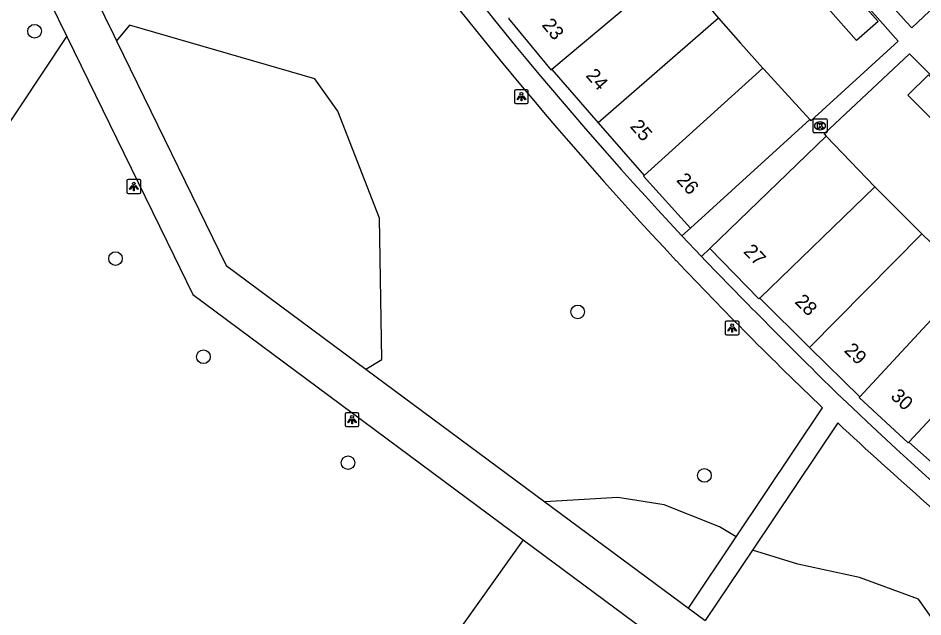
# Model space of a CAD drawing. Extents: x 160026 to 161302, y 384757 to 385701.
# Drawn here: x 160276.8 to 160341.6, y 385373.5 to 385416.5 of the extents above; entities that cross this region are included whole.
import ezdxf

# ---------------------------------------------------------------- set-up
doc = ezdxf.new("R2010")
doc.units = 0
for name, color, linetype in [('IMGEO_Boom', 7, 'Continuous'), ('IMGEO_Groenvoorziening', 7, 'Continuous'), ('IMGEO_Kolk', 7, 'Continuous'), ('IMGEO_Lichtpunt', 7, 'Continuous'), ('IMGEO_Pand', 7, 'Continuous'), ('IMGEO_Pand_nummerreeks', 7, 'Continuous'), ('IMGEO_Rijbaan_lokaal_open', 7, 'Continuous'), ('IMGEO_Voetpad_open', 7, 'Continuous')]:
    doc.layers.add(name, color=color, linetype=linetype)

msp = doc.modelspace()

# ---------------------------------------------------------------- linework, layer by layer
at = {"layer": 'IMGEO_Boom'}
for centre in [(160278.004, 385415.507), (160283.801, 385399.224), (160316.903, 385395.403), (160290.103, 385392.185), (160300.453, 385384.598), (160325.981, 385383.684)]:
    msp.add_circle(centre, 0.489, dxfattribs=at)
at = {"layer": 'IMGEO_Groenvoorziening'}
for points in [[(160301.742, 385391.306), (160302.881, 385391.991), (160302.706, 385402.128), (160299.735, 385409.79), (160298.089, 385412.09), (160284.8, 385415.949), (160283.874, 385414.83)], [(160263.246, 385389.432), (160280.314, 385415.136)], [(160328.251, 385379.283), (160327.068, 385380.008), (160323.107, 385381.576), (160319.769, 385382.102), (160314.554, 385381.8)], [(160313.003, 385379.066), (160306.615, 385370.103), (160315.68, 385363.866)], [(160348.057, 385365.324), (160341.324, 385374.825), (160337.094, 385376.363), (160332.682, 385377.332), (160329.427, 385378.337)]]:
    msp.add_lwpolyline(points, dxfattribs=at)
at = {"layer": 'IMGEO_Kolk'}
for p, q in [((160333.76, 385408.306), (160333.76, 385409.158)), ((160333.835, 385409.232), (160334.687, 385409.232)), ((160334.248, 385409.012), (160334.273, 385409.012)), ((160334.761, 385409.158), (160334.761, 385408.306)), ((160334.687, 385408.232), (160333.835, 385408.232)), ((160334.271, 385408.452), (160334.246, 385408.452))]:
    msp.add_line(p, q, dxfattribs=at)
for points in [[(160333.76, 385408.306), (160333.76, 385409.158)], [(160333.835, 385409.232), (160334.687, 385409.232)], [(160334.081, 385408.932), (160334.204, 385408.932), (160334.204, 385408.781), (160334.334, 385408.932), (160334.498, 385408.932), (160334.352, 385408.781), (160334.505, 385408.532), (160334.353, 385408.532), (160334.268, 385408.696), (160334.204, 385408.629), (160334.204, 385408.532), (160334.081, 385408.532), (160334.081, 385408.932)], [(160334.761, 385409.158), (160334.761, 385408.306)], [(160334.687, 385408.232), (160333.835, 385408.232)]]:
    msp.add_lwpolyline(points, dxfattribs=at)
for centre, start, end in [((160333.837, 385409.156), 91.55205, 178.44795), ((160333.837, 385409.156), 91.55205, 178.44795), ((160334.685, 385409.156), 1.55205, 88.44795), ((160334.685, 385409.156), 1.55205, 88.44795), ((160333.837, 385408.308), 181.55205, 268.44795), ((160333.837, 385408.308), 181.55205, 268.44795), ((160334.685, 385408.308), 271.55205, 358.44795), ((160334.685, 385408.308), 271.55205, 358.44795)]:
    msp.add_arc(centre, 0.0765, start, end, dxfattribs=at)
for centre, major_axis, ratio, start_param, end_param in [((160334.247, 385408.732), (-0.387, 0.002), 0.722429, 4.712389, 7.853982), ((160334.272, 385408.732), (-0.39, 0.002), 0.717154, 1.570796, 4.712389)]:
    msp.add_ellipse(centre, major_axis=major_axis, ratio=ratio, start_param=start_param, end_param=end_param, dxfattribs=at)
at = {"layer": 'IMGEO_Lichtpunt'}
for p, q in [((160313.272, 385411.322), (160312.464, 385411.322)), ((160313.272, 385411.322), (160312.464, 385411.322)), ((160312.37, 385411.227), (160312.37, 385410.42)), ((160312.37, 385411.227), (160312.37, 385410.42)), ((160313.366, 385410.42), (160313.366, 385411.227)), ((160313.366, 385410.42), (160313.366, 385411.227)), ((160312.464, 385410.326), (160313.272, 385410.326)), ((160312.464, 385410.326), (160313.272, 385410.326)), ((160284.62, 385404.792), (160284.62, 385403.985)), ((160284.62, 385404.792), (160284.62, 385403.985)), ((160285.522, 385404.887), (160284.714, 385404.887)), ((160285.522, 385404.887), (160284.714, 385404.887)), ((160285.616, 385403.985), (160285.616, 385404.792)), ((160285.616, 385403.985), (160285.616, 385404.792)), ((160284.714, 385403.891), (160285.522, 385403.891)), ((160284.714, 385403.891), (160285.522, 385403.891)), ((160327.467, 385394.653), (160327.467, 385393.846)), ((160327.467, 385394.653), (160327.467, 385393.846)), ((160328.369, 385394.748), (160327.561, 385394.748)), ((160328.369, 385394.748), (160327.561, 385394.748)), ((160328.463, 385393.846), (160328.463, 385394.653)), ((160328.463, 385393.846), (160328.463, 385394.653)), ((160327.561, 385393.752), (160328.369, 385393.752)), ((160327.561, 385393.752), (160328.369, 385393.752)), ((160300.243, 385388.083), (160300.243, 385387.276)), ((160300.243, 385388.083), (160300.243, 385387.276)), ((160301.145, 385388.178), (160300.337, 385388.178)), ((160301.145, 385388.178), (160300.337, 385388.178)), ((160301.239, 385387.276), (160301.239, 385388.083)), ((160301.239, 385387.276), (160301.239, 385388.083)), ((160300.337, 385387.182), (160301.145, 385387.182)), ((160300.337, 385387.182), (160301.145, 385387.182))]:
    msp.add_line(p, q, dxfattribs=at)
for points in [[(160312.744, 385410.891), (160312.783, 385410.863), (160312.595, 385410.601), (160312.557, 385410.628), (160312.744, 385410.891)], [(160312.846, 385410.843), (160312.893, 385410.843), (160312.893, 385410.521), (160312.846, 385410.521), (160312.846, 385410.843)], [(160312.956, 385410.863), (160312.994, 385410.89), (160313.181, 385410.628), (160313.142, 385410.6), (160312.956, 385410.863)], [(160284.994, 385404.456), (160285.033, 385404.428), (160284.845, 385404.166), (160284.807, 385404.193), (160284.994, 385404.456)], [(160285.096, 385404.408), (160285.143, 385404.408), (160285.143, 385404.086), (160285.096, 385404.086), (160285.096, 385404.408)], [(160285.206, 385404.428), (160285.244, 385404.455), (160285.431, 385404.193), (160285.392, 385404.165), (160285.206, 385404.428)], [(160327.841, 385394.317), (160327.88, 385394.289), (160327.692, 385394.027), (160327.654, 385394.054), (160327.841, 385394.317)], [(160327.943, 385394.269), (160327.99, 385394.269), (160327.99, 385393.947), (160327.943, 385393.947), (160327.943, 385394.269)], [(160328.053, 385394.289), (160328.091, 385394.316), (160328.278, 385394.054), (160328.239, 385394.026), (160328.053, 385394.289)], [(160300.617, 385387.747), (160300.656, 385387.719), (160300.468, 385387.457), (160300.43, 385387.484), (160300.617, 385387.747)], [(160300.719, 385387.699), (160300.766, 385387.699), (160300.766, 385387.377), (160300.719, 385387.377), (160300.719, 385387.699)], [(160300.829, 385387.719), (160300.867, 385387.746), (160301.054, 385387.484), (160301.015, 385387.456), (160300.829, 385387.719)]]:
    msp.add_lwpolyline(points, dxfattribs=at)
for centre in [(160312.869, 385411.025), (160285.119, 385404.59), (160327.966, 385394.451), (160300.742, 385387.881)]:
    msp.add_circle(centre, 0.0994, dxfattribs=at)
for centre, start, end in [((160312.464, 385411.227), 90, 180), ((160312.464, 385411.227), 90, 180), ((160313.272, 385411.227), 0, 90), ((160313.272, 385411.227), 0, 90), ((160312.464, 385410.42), 180, 270), ((160312.464, 385410.42), 180, 270), ((160313.272, 385410.42), 270, 0), ((160313.272, 385410.42), 270, 360), ((160284.714, 385404.792), 90, 180), ((160284.714, 385404.792), 90, 180), ((160285.522, 385404.792), 0, 90), ((160285.522, 385404.792), 0, 90), ((160284.714, 385403.985), 180, 270), ((160284.714, 385403.985), 180, 270), ((160285.522, 385403.985), 270, 0), ((160285.522, 385403.985), 270, 360), ((160327.561, 385394.653), 90, 180), ((160327.561, 385394.653), 90, 180), ((160328.369, 385394.653), 0, 90), ((160328.369, 385394.653), 0, 90), ((160327.561, 385393.846), 180, 270), ((160327.561, 385393.846), 180, 270), ((160328.369, 385393.846), 270, 0), ((160328.369, 385393.846), 270, 360), ((160300.337, 385388.083), 90, 180), ((160300.337, 385388.083), 90, 180), ((160301.145, 385388.083), 0, 90), ((160301.145, 385388.083), 0, 90), ((160300.337, 385387.276), 180, 270), ((160300.337, 385387.276), 180, 270), ((160301.145, 385387.276), 270, 0), ((160301.145, 385387.276), 270, 360)]:
    msp.add_arc(centre, 0.0946, start, end, dxfattribs=at)
at = {"layer": 'IMGEO_Pand'}
for points in [[(160323.835, 385420.145), (160315.053, 385412.76)], [(160323.835, 385420.145), (160326.988, 385416.448)], [(160336.395, 385418.495), (160338.421, 385416.205), (160336.875, 385414.847), (160334.851, 385417.128)], [(160312.007, 385416.457), (160311.956, 385416.415), (160315.001, 385412.717), (160315.053, 385412.76)], [(160326.988, 385416.448), (160318.368, 385408.951)], [(160326.988, 385416.448), (160328.568, 385414.646), (160330.163, 385412.858)], [(160315.053, 385412.76), (160318.368, 385408.951)], [(160321.66, 385405.168), (160330.163, 385412.858)], [(160330.163, 385412.858), (160330.231, 385412.784), (160333.539, 385409.179)], [(160342.694, 385408.779), (160340.548, 385410.931), (160342.021, 385412.394), (160344.168, 385410.249)], [(160318.368, 385408.951), (160321.66, 385405.168)], [(160333.539, 385409.179), (160324.993, 385401.411)], [(160326.36, 385399.955), (160334.705, 385407.991)], [(160334.705, 385407.991), (160338.193, 385404.357)], [(160324.993, 385401.411), (160321.611, 385405.123), (160321.66, 385405.168)], [(160329.943, 385396.39), (160338.193, 385404.357)], [(160338.193, 385404.357), (160341.543, 385401)], [(160341.543, 385401), (160333.518, 385392.861)], [(160341.543, 385401), (160344.914, 385397.748)], [(160329.943, 385396.39), (160329.885, 385396.34), (160326.36, 385399.955)], [(160344.914, 385397.748), (160337.11, 385389.316)], [(160333.518, 385392.861), (160329.943, 385396.39)], [(160337.11, 385389.316), (160333.518, 385392.861)], [(160347.019, 385392.52), (160346.808, 385392.71), (160340.616, 385386.063)], [(160340.616, 385386.063), (160340.569, 385386.012), (160337.065, 385389.267), (160337.11, 385389.316)], [(160344.373, 385382.742), (160340.616, 385386.063)]]:
    msp.add_lwpolyline(points, dxfattribs=at)
at = {"layer": 'IMGEO_Rijbaan_lokaal_open'}
for points in [[(160333.539, 385409.179), (160333.613, 385409.099), (160339.855, 385414.79), (160338.575, 385416.252), (160305.445, 385453.391), (160305.295, 385453.56), (160306.551, 385454.383), (160313.533, 385446.599), (160316.756, 385449.732)], [(160344.197, 385418.96), (160340.836, 385415.75), (160340.438, 385416.184), (160328.808, 385429.259)], [(160374.143, 385388.911), (160370.79, 385385.756), (160377.792, 385378.697), (160376.997, 385377.529), (160354.067, 385400.467), (160340.679, 385413.888), (160334.549, 385408.158), (160334.705, 385407.991)], [(160324.369, 385400.844), (160324.993, 385401.411)], [(160324.369, 385400.844), (160325.76, 385399.377)], [(160326.36, 385399.955), (160325.76, 385399.377)]]:
    msp.add_lwpolyline(points, dxfattribs=at)
at = {"layer": 'IMGEO_Voetpad_open'}
for points in [[(160272.73, 385423.976), (160277.69, 385420.517), (160279.099, 385417.628), (160280.314, 385415.136)], [(160281.103, 385420.506), (160283.68, 385415.228), (160283.874, 385414.83)], [(160280.314, 385415.136), (160287.972, 385399.436), (160289.333, 385396.646), (160313.003, 385379.066)], [(160283.874, 385414.83), (160291.732, 385398.734), (160301.742, 385391.306)], [(160301.742, 385391.306), (160314.554, 385381.8)], [(160328.251, 385379.283), (160334.436, 385388.53)], [(160335.532, 385387.443), (160329.427, 385378.337)], [(160314.554, 385381.8), (160324.833, 385374.173)], [(160313.003, 385379.066), (160321.69, 385372.616), (160317.907, 385367.108)], [(160324.833, 385374.173), (160328.251, 385379.283)], [(160329.427, 385378.337), (160326.036, 385373.28)], [(160324.833, 385374.173), (160326.036, 385373.28)]]:
    msp.add_lwpolyline(points, dxfattribs=at)
for centre, radius, start, end in [((160533.373, 385595.811), 285.823, 214.74219, 223.00997), ((160534.837, 385596.999), 289.208, 215.0728, 223.18704), ((160541.983, 385605.107), 299.969, 223.38212, 226.21967), ((160697.825, 385758.4), 517.04, 223.97797, 225.51315), ((160531.978, 385594.918), 284.218, 226.27072, 235.54857), ((160554.269, 385622.329), 320.963, 227.03876, 230.10331)]:
    msp.add_arc(centre, radius, start, end, dxfattribs=at)

# ---------------------------------------------------------------- texts
at = {"layer": 'IMGEO_Pand_nummerreeks'}
for s, rotation, p in [('23', 309.47085, (160314.29, 385415.94)), ('24', 311.0293, (160317.435, 385412.308)), ('25', 311.0293, (160320.605, 385408.665)), ('26', 312.33564, (160323.924, 385404.811)), ('27', 314.27797, (160328.724, 385399.679)), ('28', 315.37232, (160332.394, 385396.079)), ('29', 315.37232, (160335.934, 385392.585)), ('30', 317.10838, (160339.255, 385389.28))]:
    msp.add_text(s, height=1, rotation=rotation, dxfattribs=at).set_placement(p)

doc.saveas('drawing.dxf')
